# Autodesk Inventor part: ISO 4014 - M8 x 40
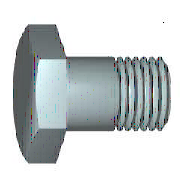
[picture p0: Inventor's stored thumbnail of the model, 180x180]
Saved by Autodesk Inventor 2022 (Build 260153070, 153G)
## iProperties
Created: 2021-02
Part Number: ISO 4014 - M8 x 40
Material: Acier inoxydable 440C
Description: Boulon à tête hexagonale - Produit de classes A et B
Document SubType Name: Modeling
Standard: ISO 4014
Designer: Fabian
Standard Revision: Fourth edition 2011-03-15
Standards Organization: ISO
Language: fr-FR
Size Designation: M8 x 40
Categories: <MemberInstance><Categories><Category DisplayName="Visserie" InternalName="e4da775c-781d-43d5-af7c-5136215cf5a6" Mnemonic="FSTN"><Category DisplayName="Vis" Int
Density: 7.75 g/cm^3
Appearance: Semi-poli
IsCustomPart: 0
Author: Fabian
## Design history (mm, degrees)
sketch "Esquisse1"
  geometry: L1 (0, 5.815)-(0, 4); L2 (18, 4)-(40, 4); L3 (40, 4)-(40, 0); L4 (40, 0)-(-0.6, 0); L5 (-8.72, 0)-(48.12, 0) reference; L6 (-0.6, 0)-(-0.6, 5.815); L7 (-0.6, 5.815)-(0, 5.815); L8 (18, 4)-(17.233, 4); L9 (17.233, 4)-(0, 4); L10 (0, -1.163)-(0, 6.978) reference
  constraints: 16 end point, 2 collinear, 2 perpendicular, 1 parallel
  dimensions: "d0" = 40 distance between parallel lines of L3 L1 (= NLG); "d1" = 22 distance from line of L2.start L3 (= GEL); "d2" = 8 diameter of L2 L4 (= GD); "d9" = 0.6001 distance between parallel lines of L6 L1 (computed from SD); "d10" = 11.63 diameter of L7 L4 (= SD2); "d13" = 0.76691 distance of L2.start L8.end (computed from GAL); "d14" = 8 diameter of L9 L4 (= BDM)
revolve "Corps" sketch "Esquisse1" stored, may be unused: angle "d12" = 90 deg
sketch "Esquisse2"
  geometry: L1 (0, 7.506)-(6.5, 3.753); L2 (6.5, 3.753)-(6.5, -3.753); L3 (6.5, -3.753)-(0, -7.506); L4 (0, -7.506)-(-6.5, -3.753); L5 (-6.5, -3.753)-(-6.5, 3.753); L6 (-6.5, 3.753)-(0, 7.506); 2 further points
  constraints: 12 end point, 1 coincident, 1 vertical, 11 other
  dimensions: "d11" = 13 distance between parallel lines of L5 L2 (= SW)
extrude "Tête" join sketch "Esquisse2" distance "d3" = 4.7 (= KOH - SD); taper "d4" = 0 deg
sketch "Esquisse4"
  geometry: L1 (-5.3, 6.5)-(-5.3, 7.506); L2 (-5.3, 7.506)-(-4.72, 7.506); L3 (-4.72, 7.506)-(-5.3, 6.5); L4 (-6.24, 0)-(0.34, 0) reference; L5 (-0.6, 7.506)-(-5.3, 7.506) reference; L6 (-5.3, 3.753)-(-5.3, 7.506) reference
  constraints: 6 end point, 2 collinear, 1 perpendicular, 1 vertical
  dimensions: "d5" = 30 deg angle of L3 L1 (= ANG1); "d19" = 13 diameter of L1.start L4 (= SW0)
revolve "Chanfrein1" sketch "Esquisse4" stored, may be unused: angle "d21" = 90 deg
workplane "Work Plane1"
body "Solid1"
feature "Filetage" dims "d15" = 22 (= GEL), "d16" = 0
chamfer "Chanfrein2" distance "d6" = 0.76681 (= -0.5 x SPD + 0.5 x GD); stored, may be unused: second distance "d7" = 0.76691 (computed from GUL), angle "d55" = 45 deg
other parameters: "NLG" = 40 [user parameter; used in 1 equation term], "GD" = 8 (= NND) [user parameter; used in 2 equation terms], "BDM" = 8 (= NND) [user parameter; used in 1 equation term], "KOH" = 5.3 [user parameter; used in 1 equation term], "GEL" = 22 [user parameter; used in 2 equation terms], "SW" = 13 [user parameter; used in 3 equation terms], "SW0" = 13 (= SW) [user parameter; used in 1 equation term], "SPD" = 6.46637 (= NND - 1.2269 x PTC) [user parameter; used in 1 equation term], "SD2" = 11.63 [user parameter; used in 2 equation terms], "SD" = 0.6 [user parameter; used in 2 equation terms], "ANG1" = 30 deg [user parameter; used in 1 equation term], "GAL" = 0.76681 (= 0.61345 x PTC) [user parameter; used in 1 equation term], "GUL" = 0.76681 (= 0.61345 x PTC) [user parameter; used in 1 equation term], "d8" = 0, "RR" = 0.4 [user parameter], "d57" = 0, "d58" = 0, "TPU" = 8 (computed from PTC) [user parameter], "GD1" = 6.46637 (= THREADDIA - 1.2269 x PTC) [user parameter], "THREADDIA" = 8 [user parameter; used in 1 equation term], "SDH" = 11.63 (= SD2) [user parameter], "TOA" = 30 deg [user parameter], "PTC" = 1.25 [user parameter; used in 5 equation terms], "NND" = 8 [user parameter; used in 3 equation terms], "E0" = 15.015 (= 1.155 x SW) [user parameter]
